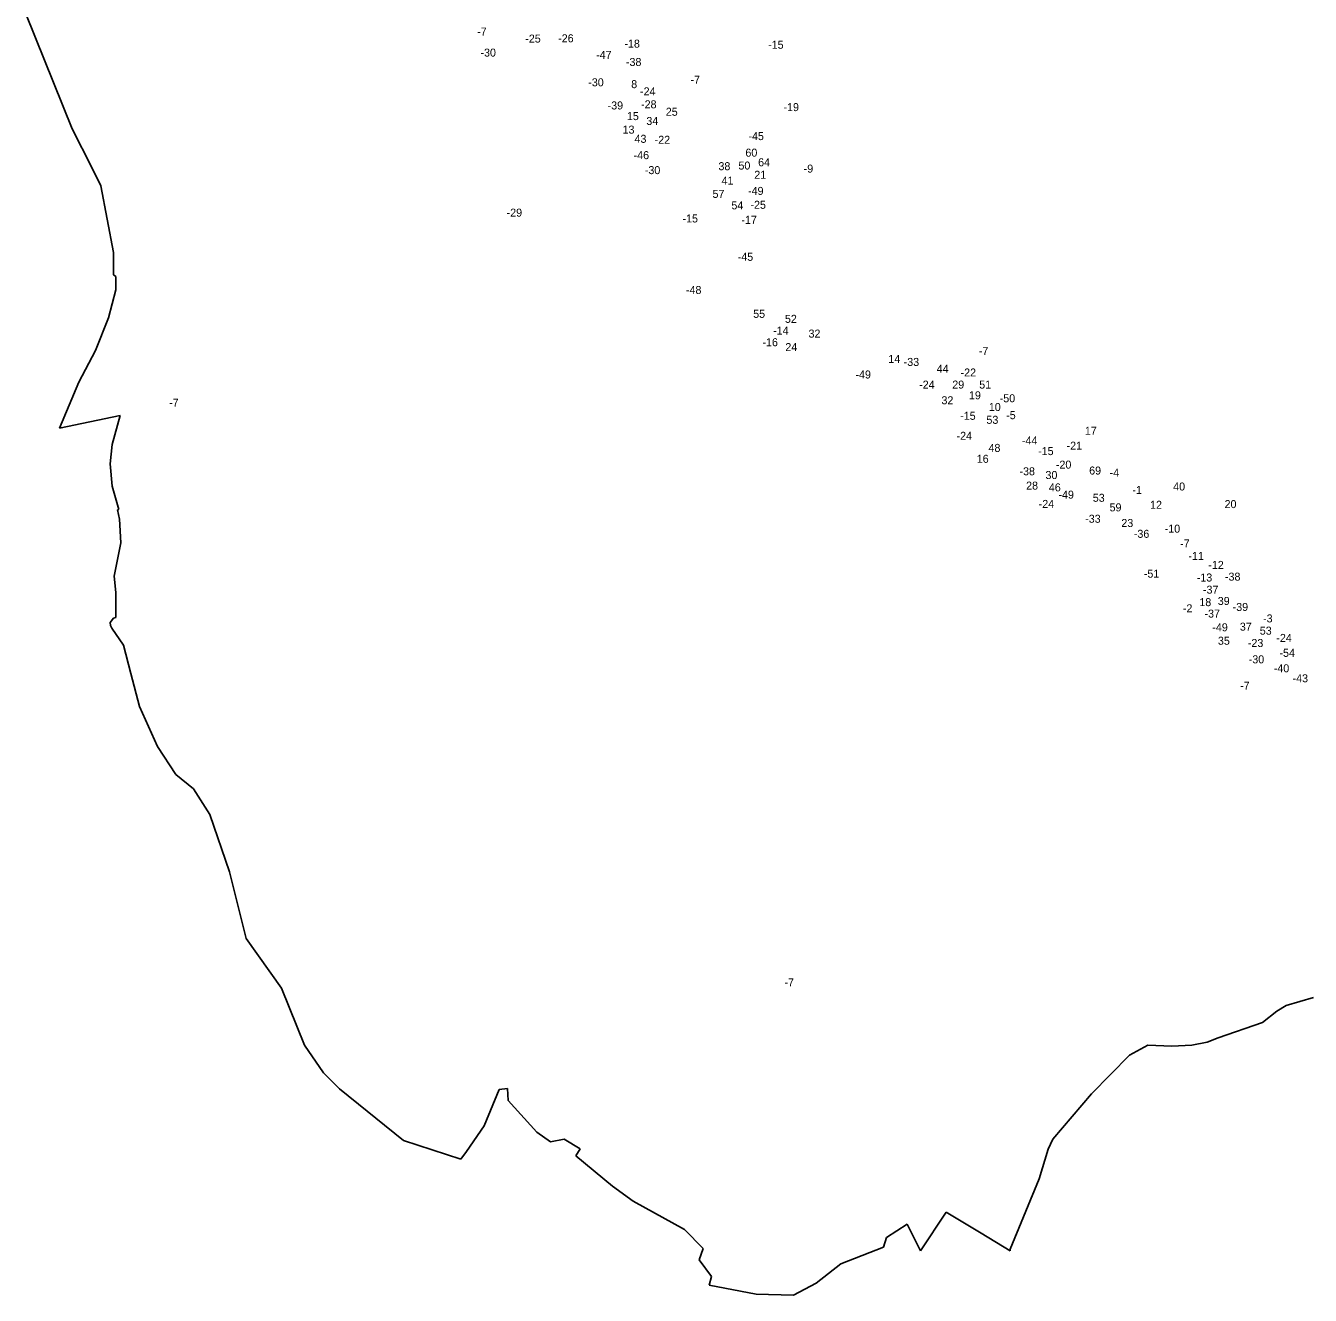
# Model space of a CAD drawing. Extents: x -788458 to -784980, y -976879 to -973650.
# Drawn here: x -788328 to -786723, y -976879 to -975293 of the extents above; entities that cross this region are included whole.
import ezdxf

# ---------------------------------------------------------------- set-up
doc = ezdxf.new("R2010")
doc.units = 0
for name, color, linetype in [('Vrstva 13', 7, 'Continuous'), ('Vrstva 24', 7, 'Continuous'), ('Vrstva 63', 7, 'Continuous')]:
    doc.layers.add(name, color=color, linetype=linetype)

msp = doc.modelspace()

# ---------------------------------------------------------------- linework, layer by layer
at = {"layer": 'Vrstva 13'}
for p, q in [((-788270, -975422.2), (-788328.2, -975278.5)), ((-788245.4, -975470.5), (-788270, -975422.2)), ((-788234.2, -975493.4), (-788245.4, -975470.5)), ((-788218.6, -975576.5), (-788234.2, -975493.4)), ((-788218.4, -975604.5), (-788218.6, -975576.5)), ((-788215.7, -975606.4), (-788218.4, -975604.5)), ((-788215.7, -975623.3), (-788215.7, -975606.4)), ((-788224.6, -975658), (-788215.7, -975623.3)), ((-788241, -975699.1), (-788224.6, -975658)), ((-788261.8, -975738.6), (-788241, -975699.1)), ((-788285.8, -975795.9), (-788261.8, -975738.6)), ((-788210, -975780.3), (-788285.8, -975795.9)), ((-788220.2, -975816.5), (-788210, -975780.3)), ((-788222.7, -975840.4), (-788220.2, -975816.5)), ((-788220, -975868.6), (-788222.7, -975840.4)), ((-788211.7, -975897.5), (-788220, -975868.6)), ((-788213.3, -975898.1), (-788211.7, -975897.5)), ((-788211.1, -975909.8), (-788213.3, -975898.1)), ((-788209.4, -975939.1), (-788211.1, -975909.8)), ((-788217.5, -975981), (-788209.4, -975939.1)), ((-788215.6, -976001.4), (-788217.5, -975981)), ((-788215.4, -976032.4), (-788215.6, -976001.4)), ((-788222.7, -976038.9), (-788218.3, -976033.2)), ((-788222.1, -976042.4), (-788222.7, -976038.9)), ((-788218.3, -976033.2), (-788215.4, -976032.4)), ((-788220.6, -976045.7), (-788222.1, -976042.4)), ((-788205.9, -976067.2), (-788220.6, -976045.7)), ((-788196.7, -976102.4), (-788205.9, -976067.2)), ((-788185.9, -976143.8), (-788196.7, -976102.4)), ((-788163.4, -976193.6), (-788185.9, -976143.8)), ((-788140.5, -976228.5), (-788163.4, -976193.6)), ((-788118.5, -976246.4), (-788140.5, -976228.5)), ((-788097.9, -976278.5), (-788118.5, -976246.4)), ((-788073.6, -976350.1), (-788097.9, -976278.5)), ((-788052.6, -976433.3), (-788073.6, -976350.1)), ((-788008.7, -976495.5), (-788052.6, -976433.3)), ((-787979.8, -976566.7), (-788008.7, -976495.5)), ((-786753, -976517.2), (-786764.6, -976524.1)), ((-786718.7, -976507.3), (-786753, -976517.2)), ((-786782.5, -976538.5), (-786838.2, -976557.7)), ((-786764.6, -976524.1), (-786782.5, -976538.5)), ((-787955.9, -976601.2), (-787979.8, -976566.7)), ((-786925.7, -976566.6), (-786948.6, -976579.1)), ((-786895.8, -976567.9), (-786925.7, -976566.6)), ((-786871, -976566.8), (-786895.8, -976567.9)), ((-786851.9, -976562.8), (-786871, -976566.8)), ((-786838.2, -976557.7), (-786851.9, -976562.8)), ((-786948.6, -976579.1), (-786996.1, -976627.4)), ((-787935.9, -976621.2), (-787955.9, -976601.2)), ((-787855.9, -976685.7), (-787935.9, -976621.2)), ((-787736.4, -976622.2), (-787755.4, -976667.6)), ((-787726, -976620.8), (-787736.4, -976622.2)), ((-787726, -976620.8), (-787725.4, -976635.8)), ((-786996.1, -976627.4), (-787044.7, -976684.1)), ((-787725.4, -976635.8), (-787689.4, -976675.3)), ((-787755.4, -976667.6), (-787777.4, -976699.5)), ((-787689.4, -976675.3), (-787672.5, -976687.4)), ((-787784.3, -976709.1), (-787855.9, -976685.7)), ((-787672.5, -976687.4), (-787655.1, -976684.3)), ((-787655.1, -976684.3), (-787635.5, -976696.2)), ((-787635.5, -976696.2), (-787640.7, -976704.9)), ((-787050.5, -976696.8), (-787061.8, -976733.8)), ((-787044.7, -976684.1), (-787050.5, -976696.8)), ((-787777.4, -976699.5), (-787784.3, -976709.1)), ((-787640.7, -976704.9), (-787594.9, -976743)), ((-787594.9, -976743), (-787568.9, -976761.5)), ((-787061.8, -976733.8), (-787097.9, -976821.7)), ((-787568.9, -976761.5), (-787504.8, -976796.9)), ((-787210.1, -976823.6), (-787177.8, -976775.3)), ((-787177.8, -976775.3), (-787134.1, -976801.7)), ((-787252.5, -976807.1), (-787226.5, -976790.5)), ((-787226.5, -976790.5), (-787210.1, -976823.6)), ((-787504.8, -976796.9), (-787481.7, -976820.7)), ((-787256.1, -976819), (-787252.5, -976807.1)), ((-787134.1, -976801.7), (-787098, -976823.8)), ((-787481.7, -976820.7), (-787486.7, -976835)), ((-787309.4, -976840), (-787256.1, -976819)), ((-787097.9, -976821.7), (-787098, -976823.8)), ((-787486.7, -976835), (-787471.1, -976855.6)), ((-787340.4, -976864.2), (-787309.4, -976840)), ((-787471.1, -976855.6), (-787474.2, -976866.3)), ((-787474.2, -976866.3), (-787415.3, -976877.9)), ((-787368.5, -976879.2), (-787340.4, -976864.2)), ((-787415.3, -976877.9), (-787368.5, -976879.2))]:
    msp.add_line(p, q, dxfattribs=at)

# ---------------------------------------------------------------- texts
at = {"layer": 'Vrstva 24'}
for s, p in [('-7', (-787764.1, -975305.6)), ('-25', (-787703.9, -975314.3)), ('-26', (-787662.8, -975313.9)), ('-18', (-787580, -975320.6)), ('-15', (-787400.4, -975322)), ('-30', (-787759.9, -975331.8)), ('-47', (-787615.4, -975334.7)), ('-38', (-787578.1, -975343.5)), ('-30', (-787625.2, -975368.9)), ('-7', (-787497.4, -975365.6)), ('-24', (-787560.5, -975380.2)), ('-39', (-787601, -975397.8)), ('-28', (-787559.2, -975396.4)), ('-19', (-787381.2, -975399.9)), ('-22', (-787542.2, -975440.7)), ('-45', (-787425, -975436.1)), ('60', (-787428.8, -975456.8)), ('-46', (-787568.5, -975459.9)), ('50', (-787437.5, -975472.9)), ('64', (-787412.9, -975468.8)), ('-30', (-787554.5, -975478.6)), ('-9', (-787356, -975476.7)), ('41', (-787458.6, -975491.7)), ('-49', (-787425.5, -975504.6)), ('57', (-787469.9, -975508.3)), ('-29', (-787727.2, -975531.7)), ('54', (-787446.3, -975522.6)), ('-25', (-787422.5, -975521.9)), ('-15', (-787507.4, -975539)), ('-17', (-787433.8, -975540.7)), ('-45', (-787438.4, -975586.9)), ('-48', (-787503.1, -975628.3)), ('55', (-787419.1, -975658.1)), ('-14', (-787394.2, -975679.1)), ('-16', (-787407.5, -975693.6)), ('-7', (-787137.1, -975704.5)), ('-33', (-787231, -975718.2)), ('-49', (-787291.3, -975733.9)), ('-22', (-787159.9, -975731.4)), ('-24', (-787211.7, -975746.6)), ('-7', (-788149, -975769.1)), ('-50', (-787111, -975763.6)), ('-15', (-787160.4, -975785.5)), ('53', (-787127.6, -975790.5)), ('-5', (-787102.9, -975784.7)), ('-24', (-787164.9, -975810.5)), ('17', (-787004.6, -975804.2)), ('48', (-787125, -975825.6)), ('-44', (-787083.2, -975816.3)), ('-21', (-787027.4, -975822.8)), ('-15', (-787063, -975829.6)), ('-38', (-787086.3, -975854.8)), ('-20', (-787040.8, -975846.5)), ('69', (-786999.2, -975853.9)), ('-4', (-786973.6, -975856.5)), ('-49', (-787037.6, -975884)), ('53', (-786994.7, -975887.9)), ('-1', (-786945.2, -975878.2)), ('-24', (-787062.3, -975895.6)), ('59', (-786973.7, -975899.9)), ('-33', (-787004.2, -975914.1)), ('-36', (-786943.4, -975932.9)), ('-10', (-786904.8, -975926.5)), ('-7', (-786885.6, -975945)), ('-11', (-786875.2, -975960.6)), ('-51', (-786930.9, -975982.7)), ('-12', (-786850.3, -975971.8)), ('-38', (-786829.5, -975986.4)), ('-13', (-786864.7, -975987.5)), ('-37', (-786857, -976002.7)), ('-2', (-786882.1, -976026)), ('-37', (-786855.1, -976032.6)), ('-39', (-786819.9, -976024.3)), ('-49', (-786845.3, -976049.7)), ('-3', (-786781.9, -976038.6)), ('53', (-786786, -976053.9)), ('-24', (-786765.3, -976063)), ('-23', (-786800.9, -976069.3)), ('-54', (-786761.4, -976081.6)), ('-30', (-786799.8, -976089.7)), ('-40', (-786768.5, -976100.9)), ('-43', (-786745, -976113.4)), ('-7', (-786810.6, -976122.6)), ('-7', (-787380, -976493.2))]:
    msp.add_text(s, height=10, dxfattribs=at).set_placement(p)
at = {"layer": 'Vrstva 63'}
for s, p in [('8', (-787571.5, -975371.2)), ('25', (-787528.3, -975405.7)), ('15', (-787576.9, -975411.1)), ('34', (-787552.6, -975417.2)), ('13', (-787582.3, -975428)), ('43', (-787567.4, -975439.5)), ('38', (-787462.5, -975473.7)), ('21', (-787417.7, -975484.4)), ('52', (-787379.4, -975664.4)), ('32', (-787349.9, -975682.8)), ('24', (-787378.9, -975699.7)), ('14', (-787250.2, -975714.5)), ('44', (-787189.7, -975726.7)), ('29', (-787170.3, -975746.5)), ('19', (-787149.4, -975759.9)), ('51', (-787136.6, -975746.5)), ('32', (-787183.8, -975766.1)), ('10', (-787124.6, -975774.5)), ('16', (-787139.7, -975839.2)), ('28', (-787078, -975872.7)), ('30', (-787053.8, -975859.5)), ('40', (-786894.2, -975873.8)), ('46', (-787049.6, -975874.9)), ('12', (-786923.1, -975896.7)), ('20', (-786830, -975895.8)), ('23', (-786959, -975919.4)), ('18', (-786861.5, -976018.3)), ('39', (-786838.5, -976016.8)), ('37', (-786810.9, -976048.9)), ('35', (-786838.3, -976066.5))]:
    msp.add_text(s, height=10, dxfattribs=at).set_placement(p)

doc.saveas('drawing.dxf')
